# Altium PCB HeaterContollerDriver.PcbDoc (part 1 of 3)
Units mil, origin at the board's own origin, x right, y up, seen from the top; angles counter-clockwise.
Board outline 11550 x 4775 mil, 6 copper layers (Top Layer, GND1, P, N, GND2, Bottom Layer), stack 62.668 mil thick; 274 components, 133 nets, 711 pads, 145 vias.
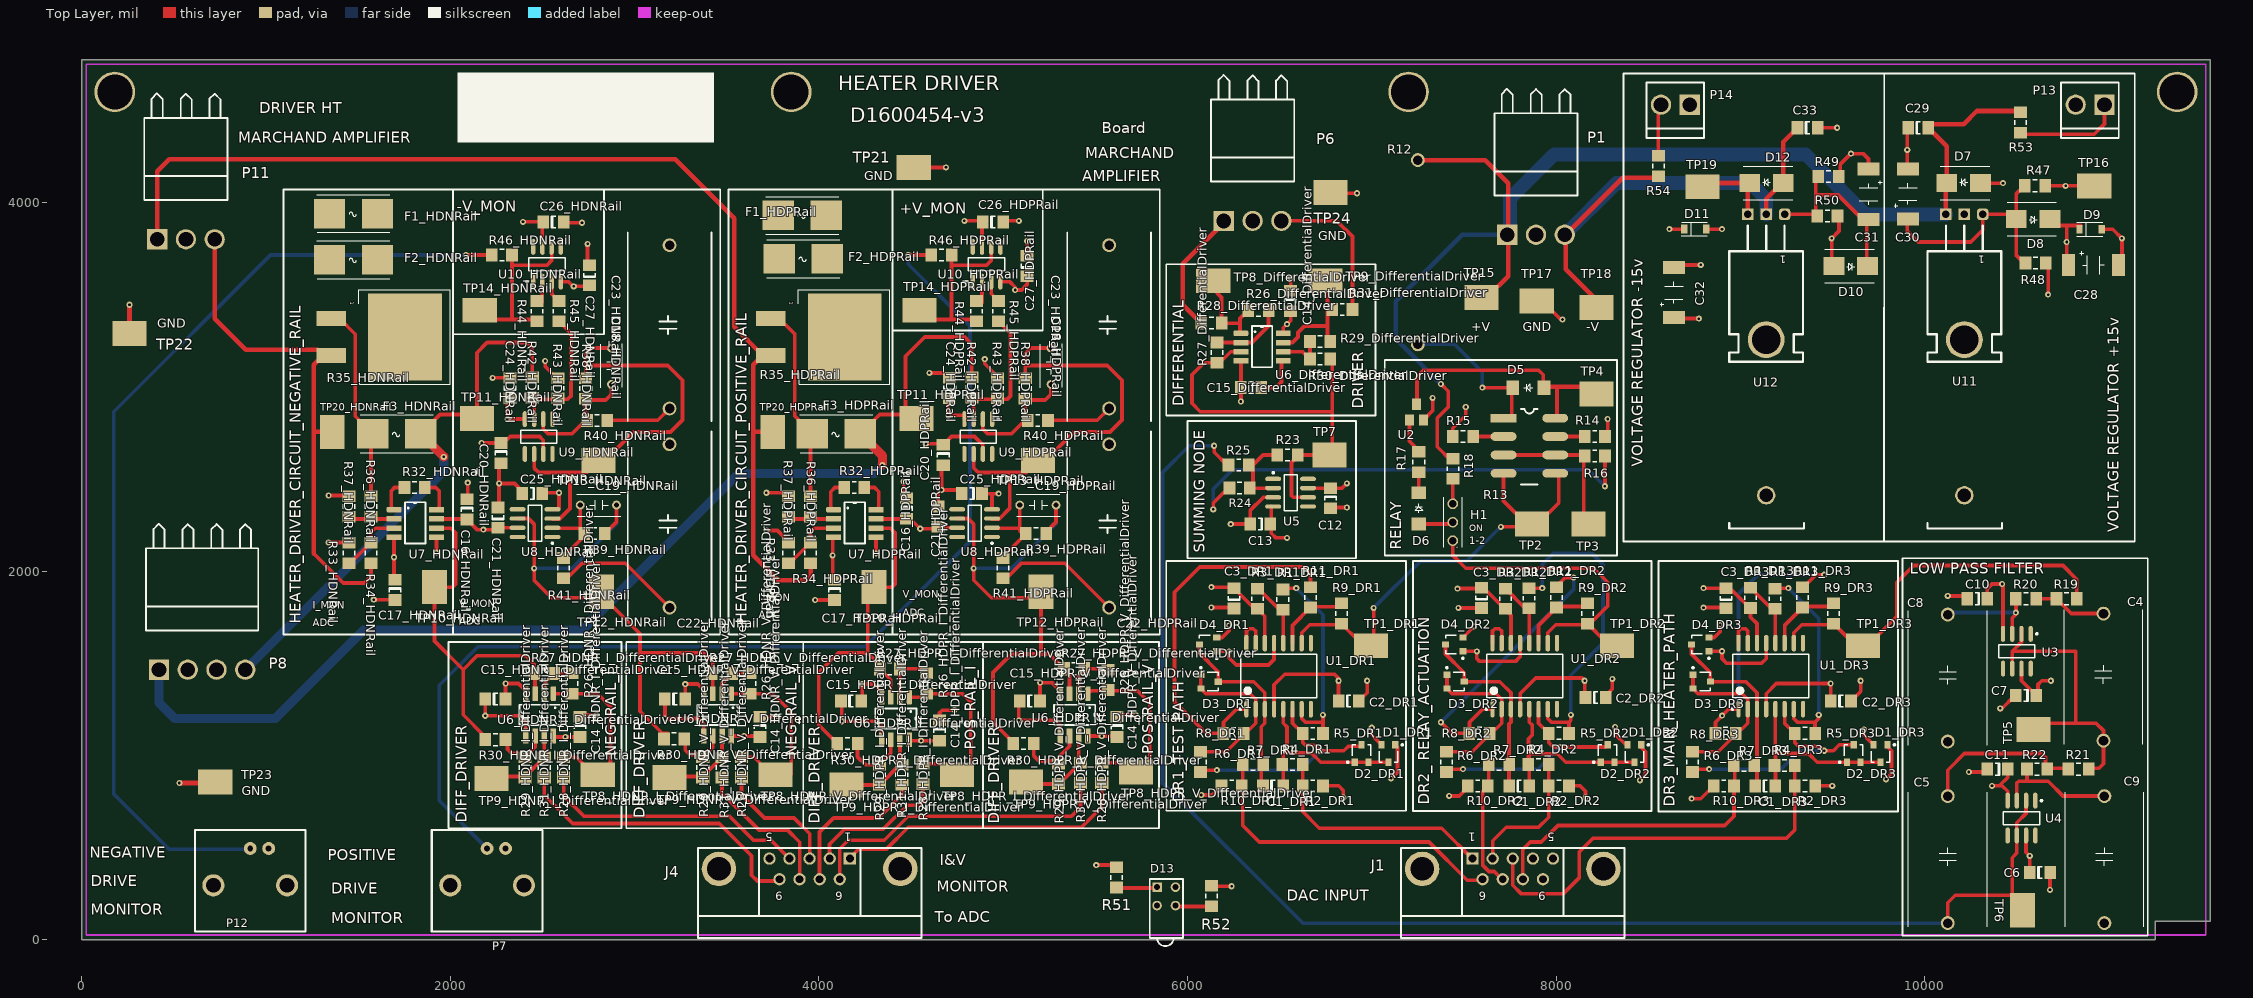
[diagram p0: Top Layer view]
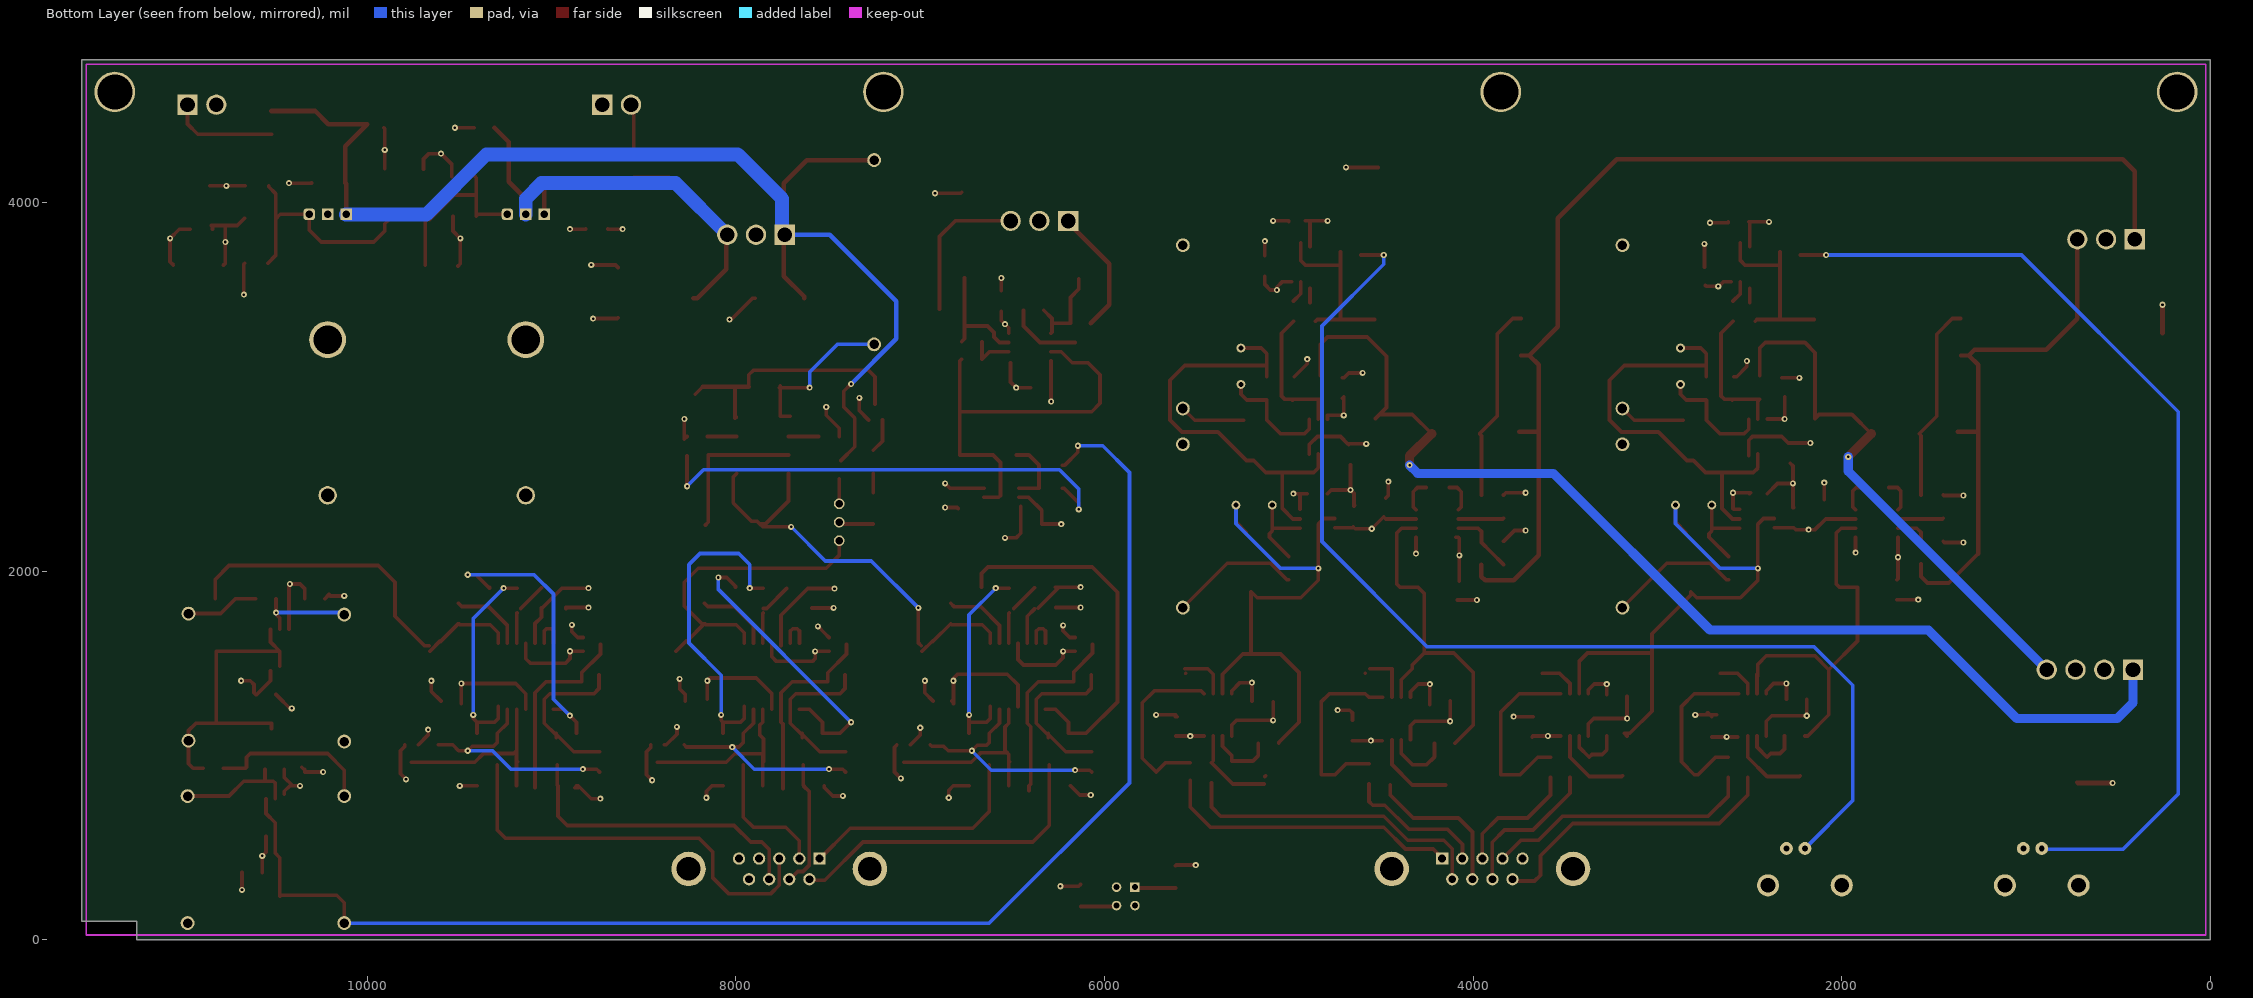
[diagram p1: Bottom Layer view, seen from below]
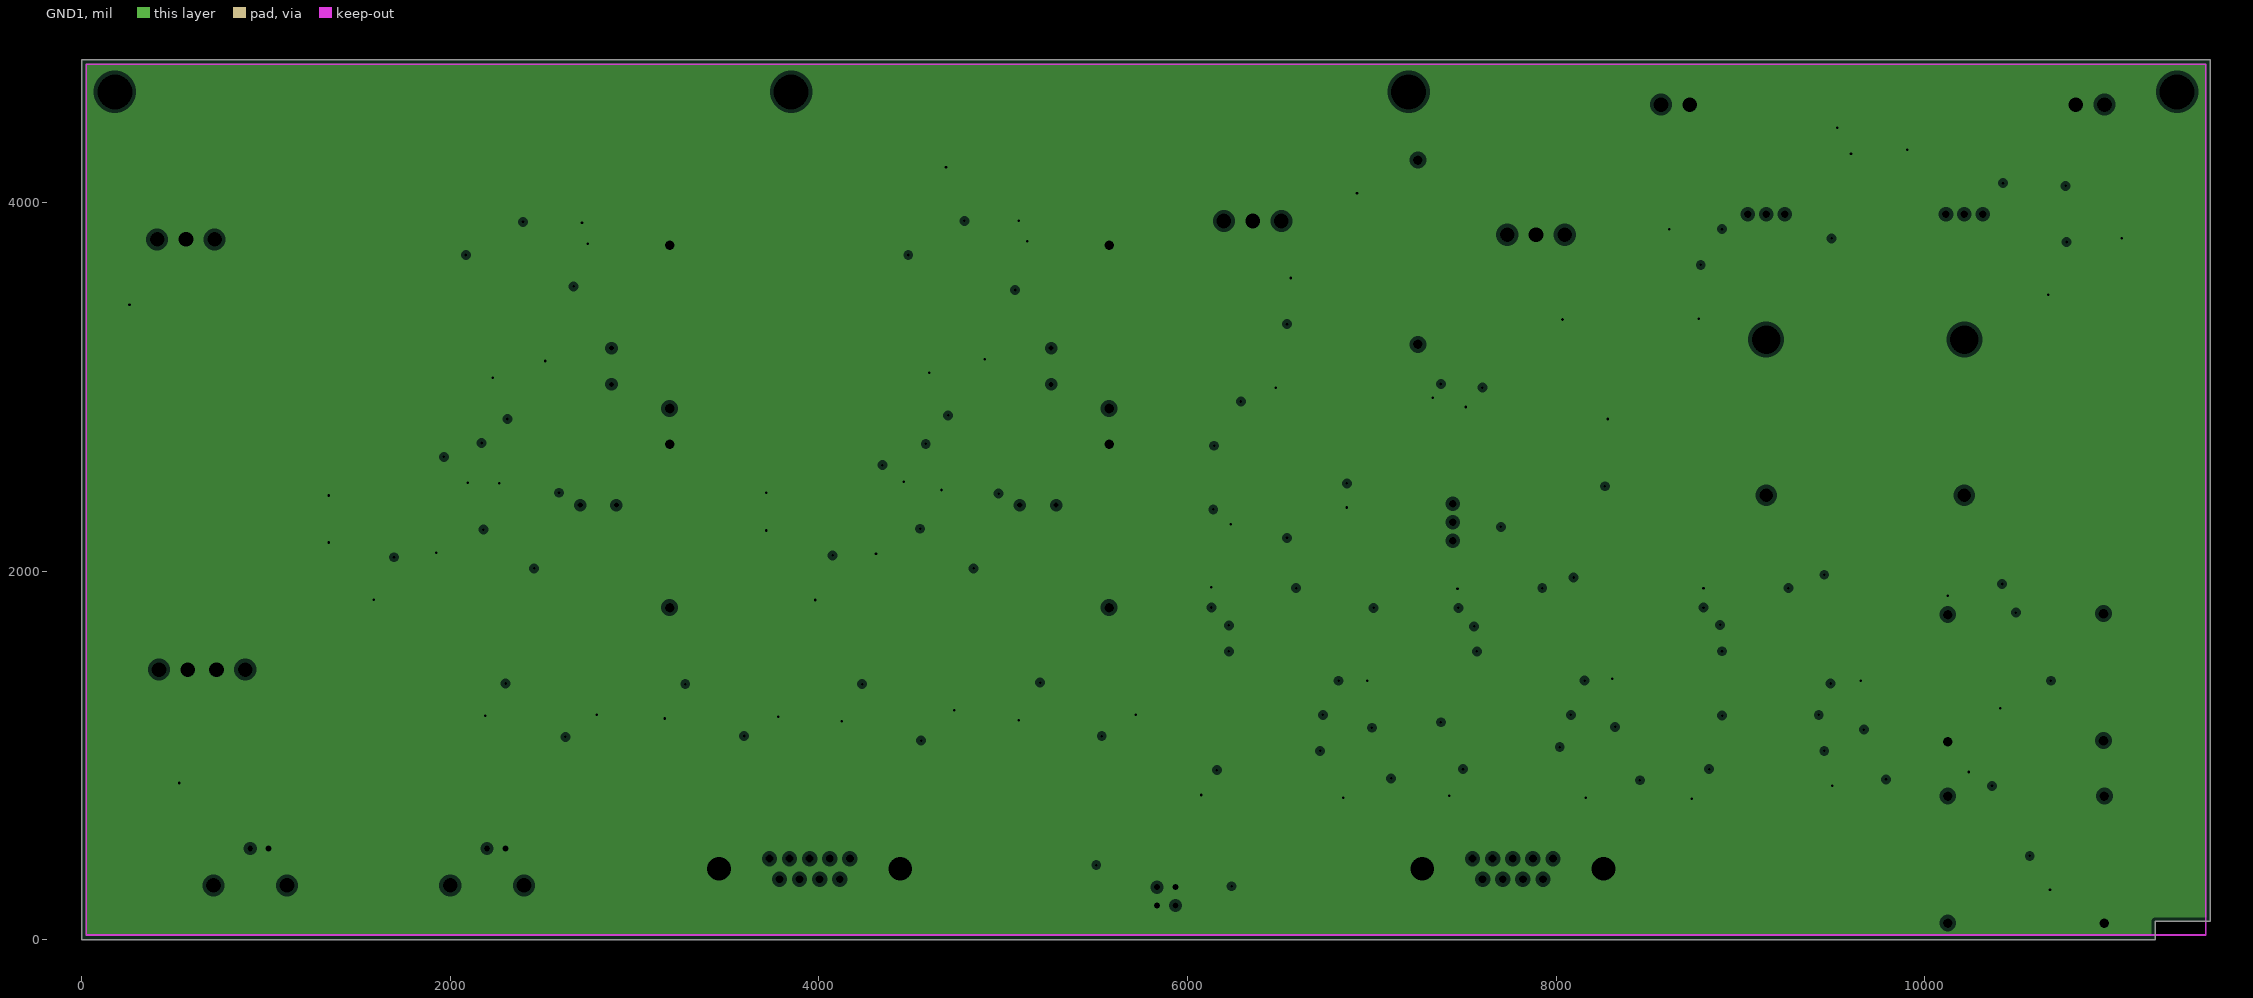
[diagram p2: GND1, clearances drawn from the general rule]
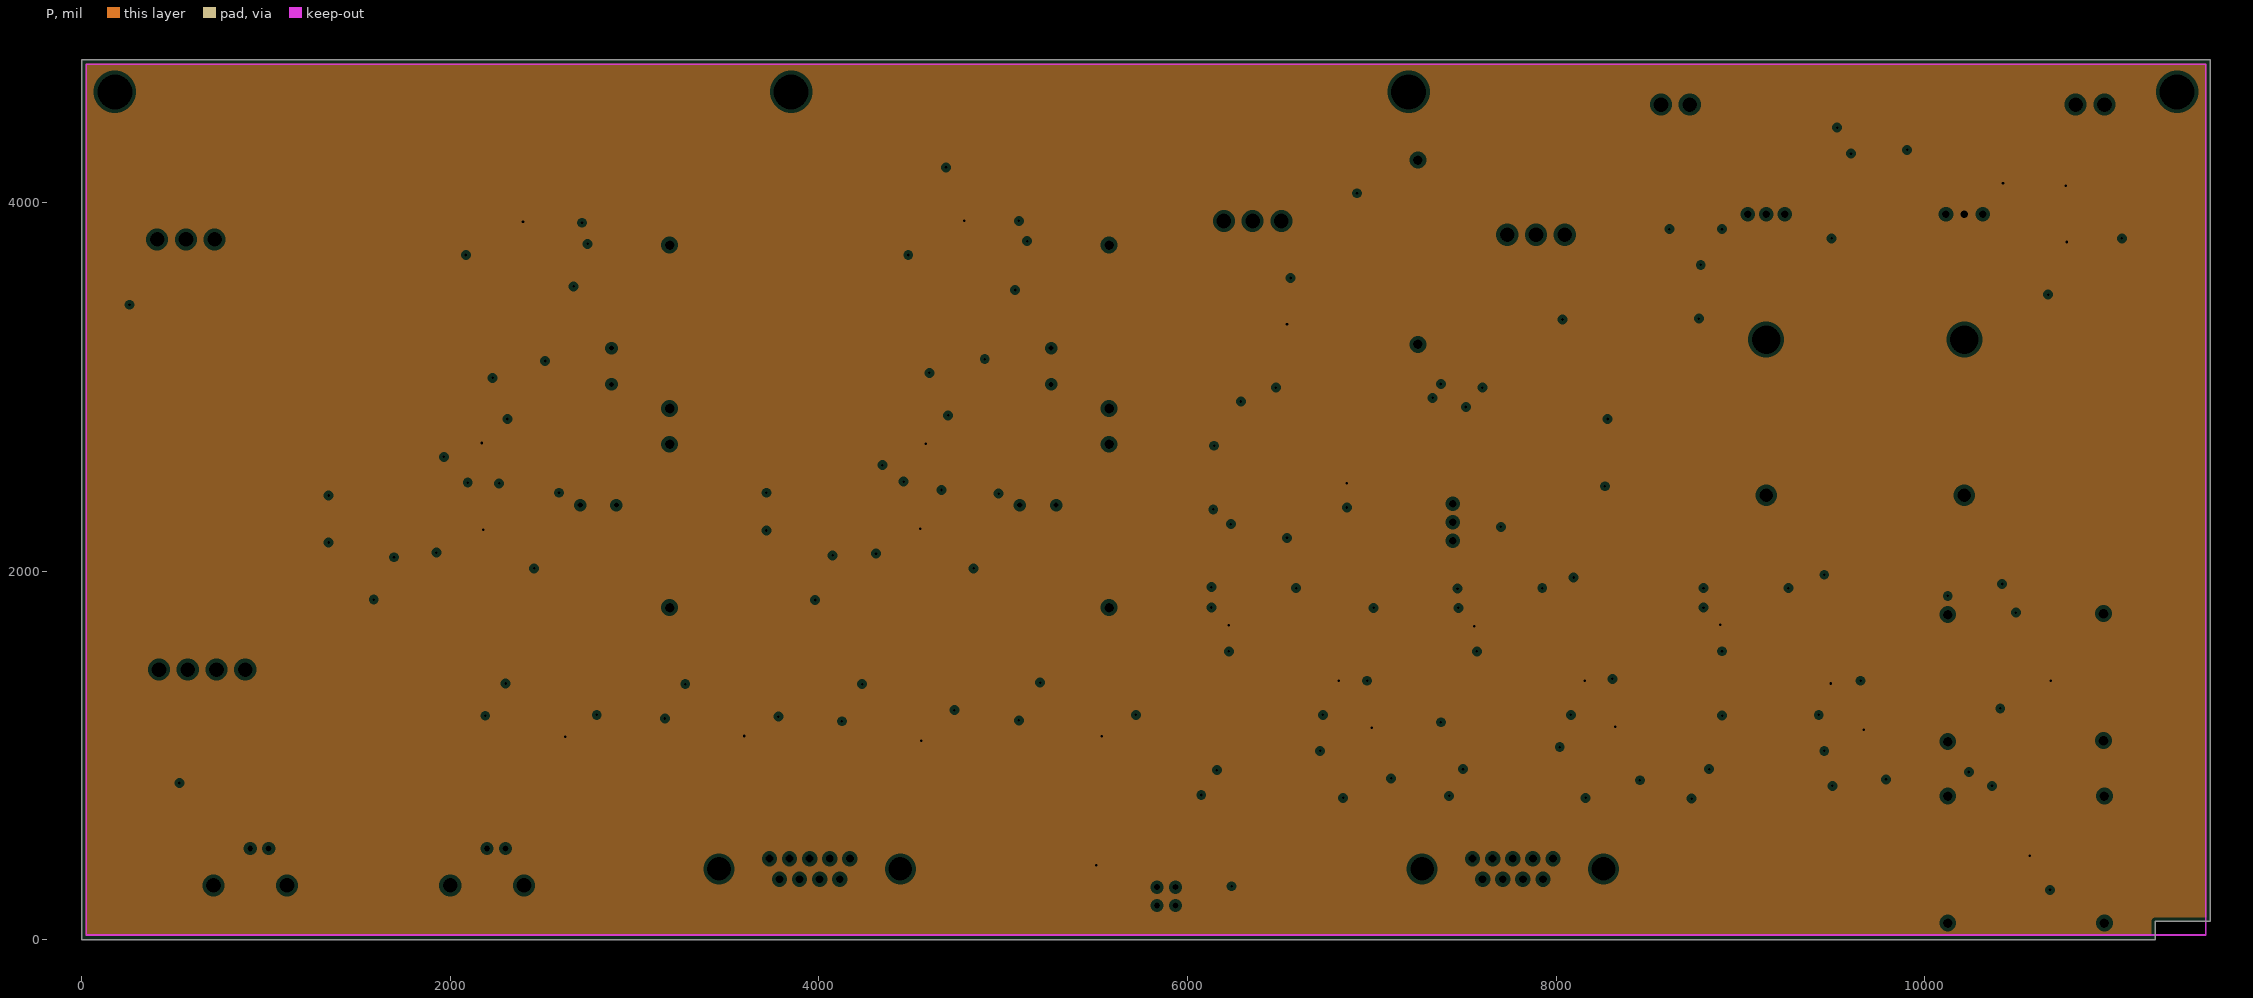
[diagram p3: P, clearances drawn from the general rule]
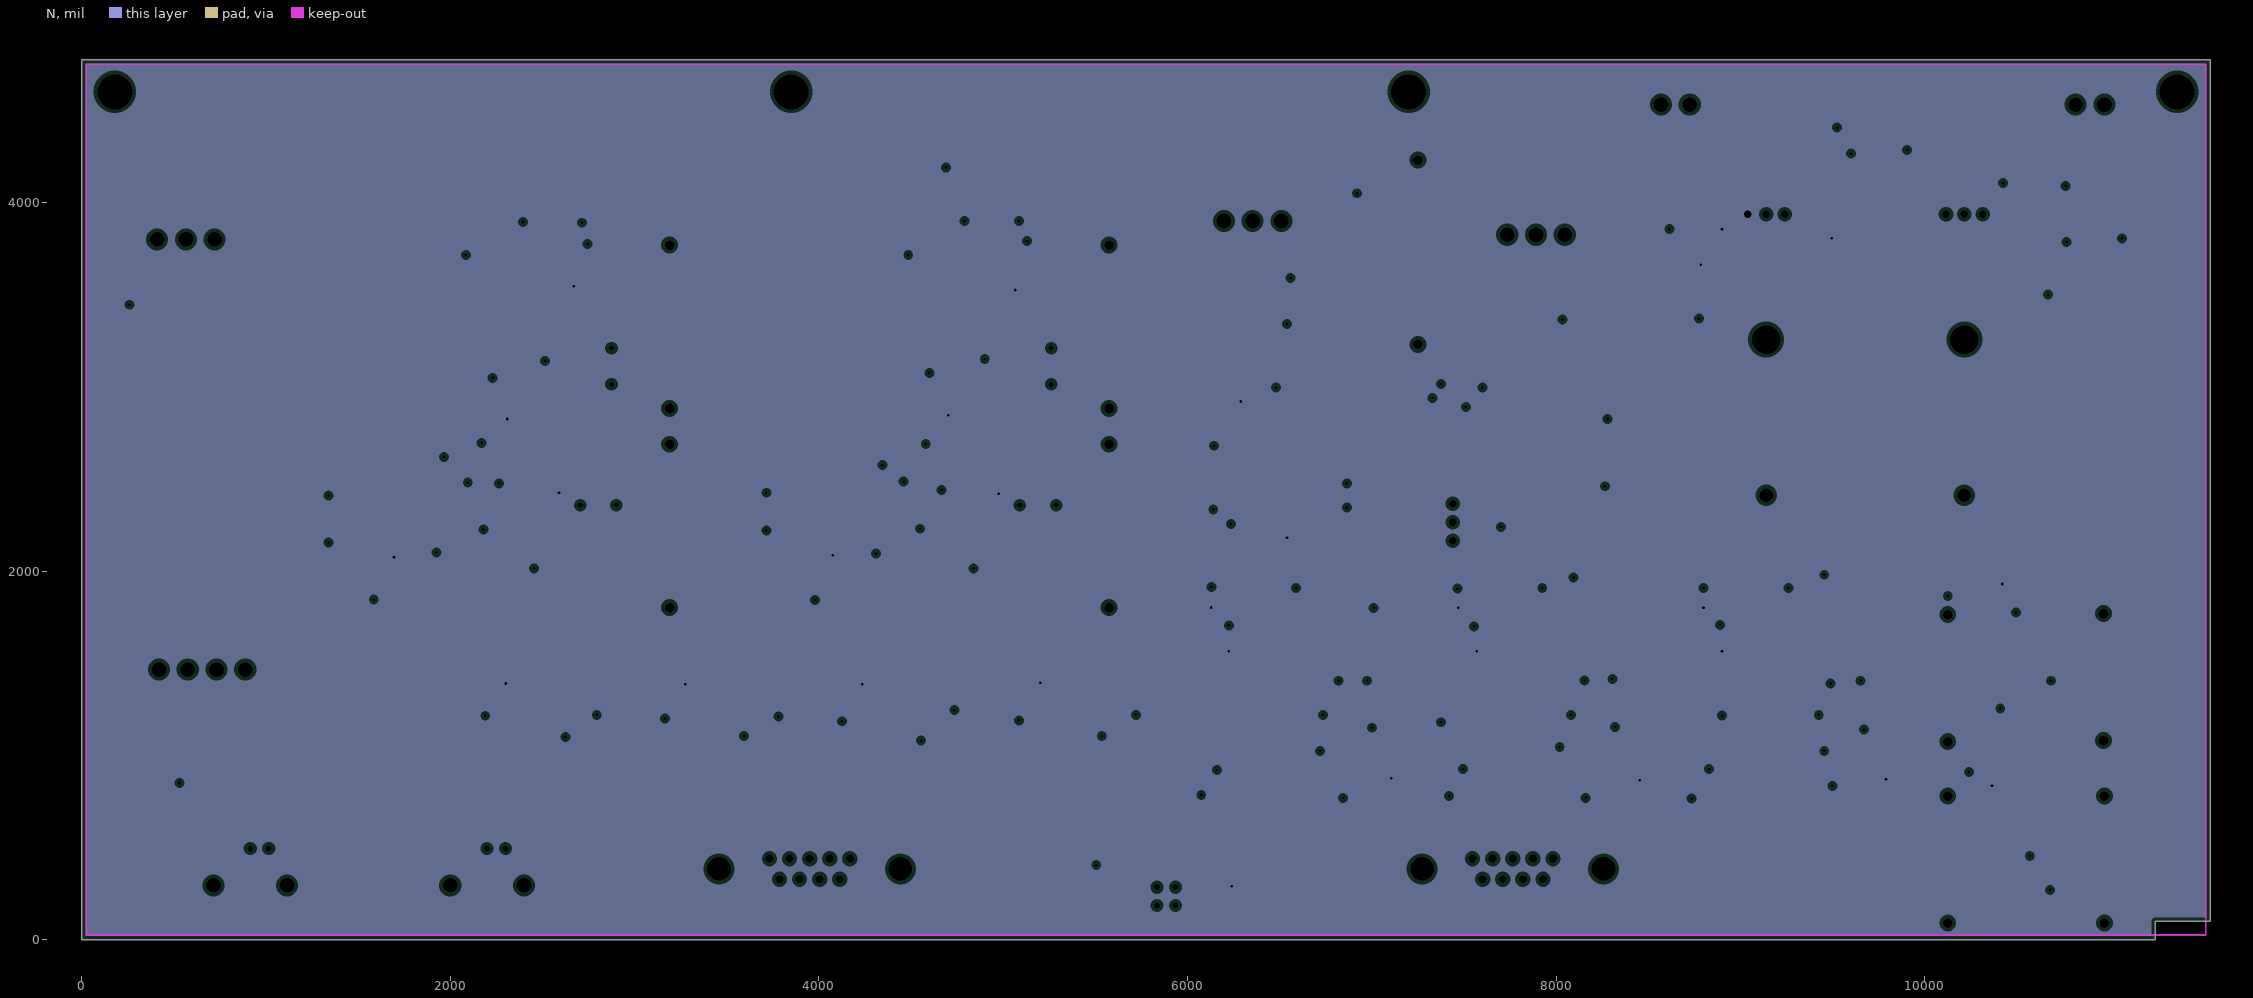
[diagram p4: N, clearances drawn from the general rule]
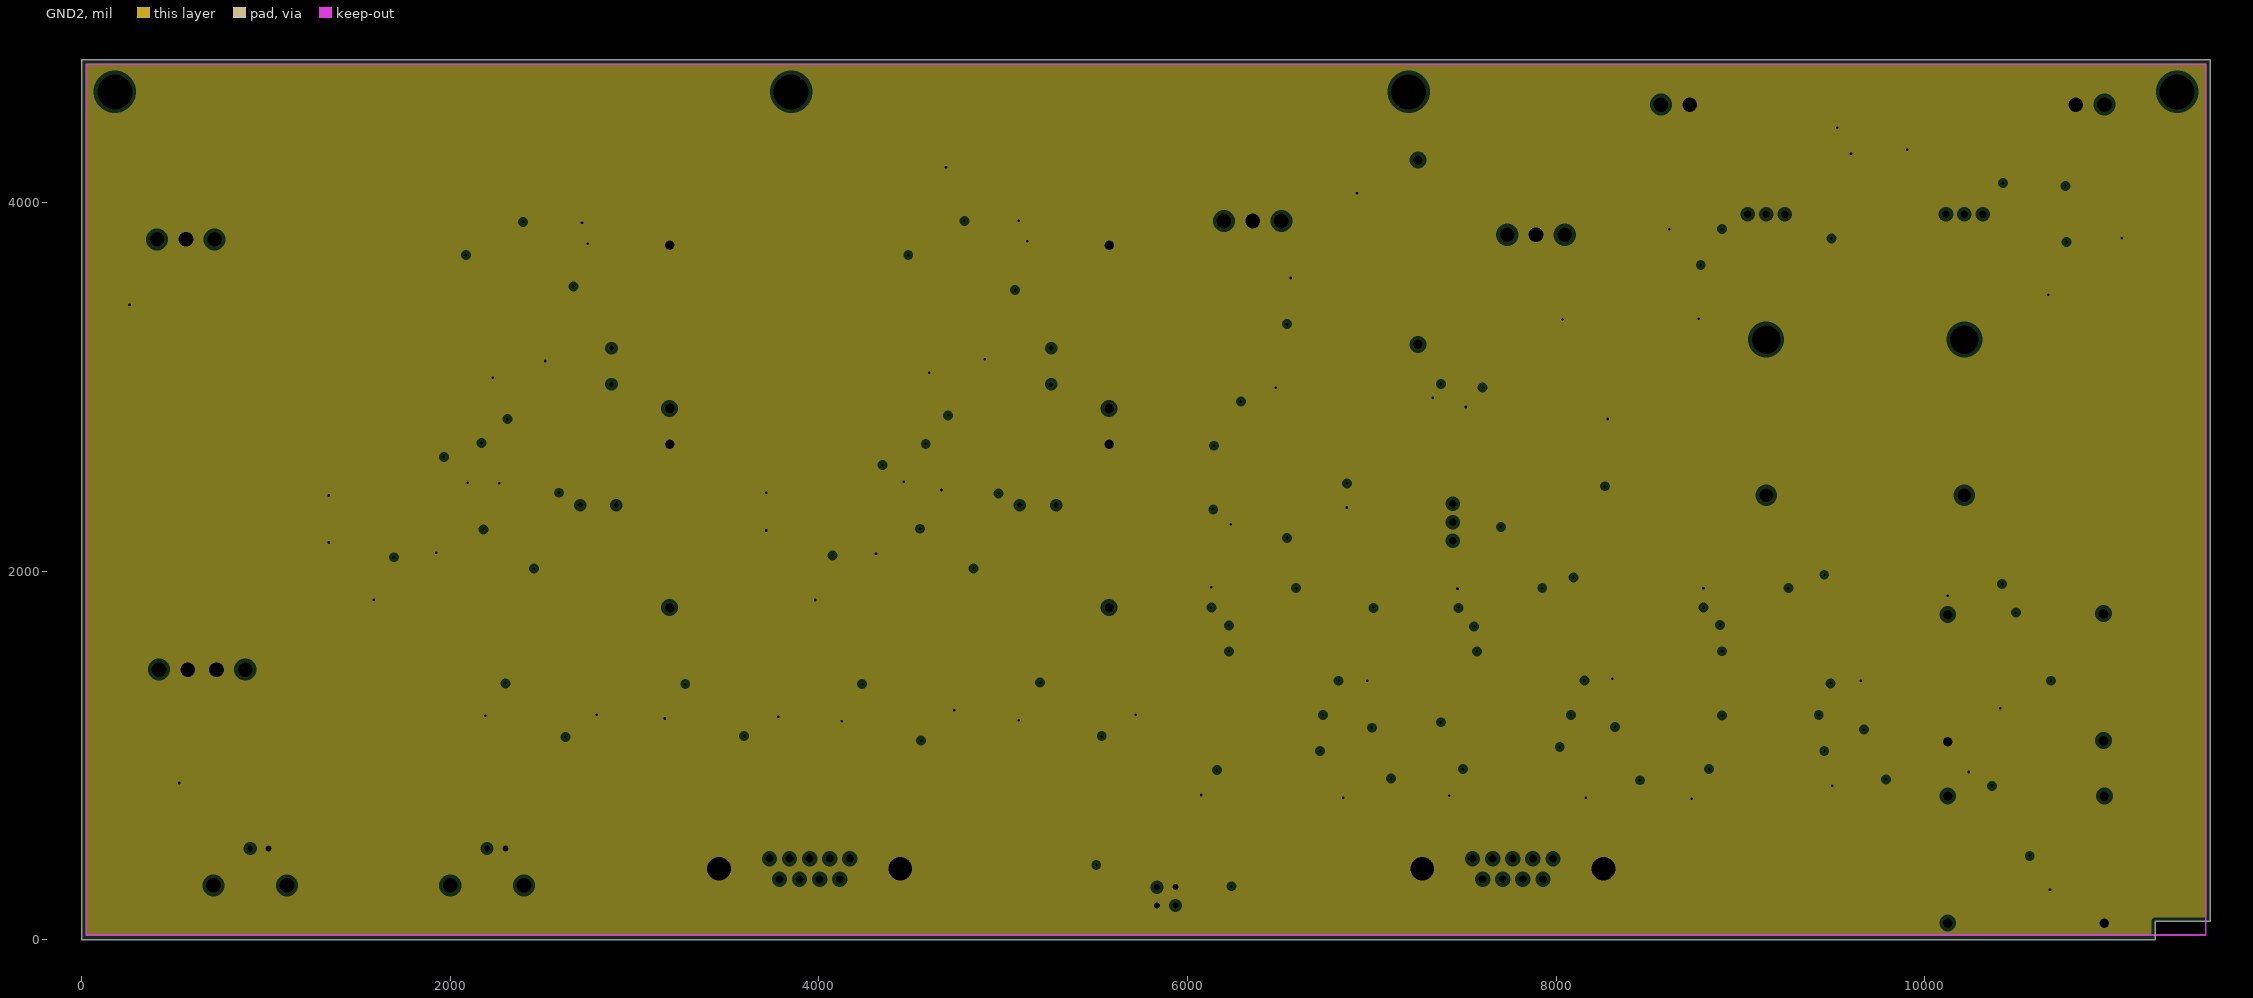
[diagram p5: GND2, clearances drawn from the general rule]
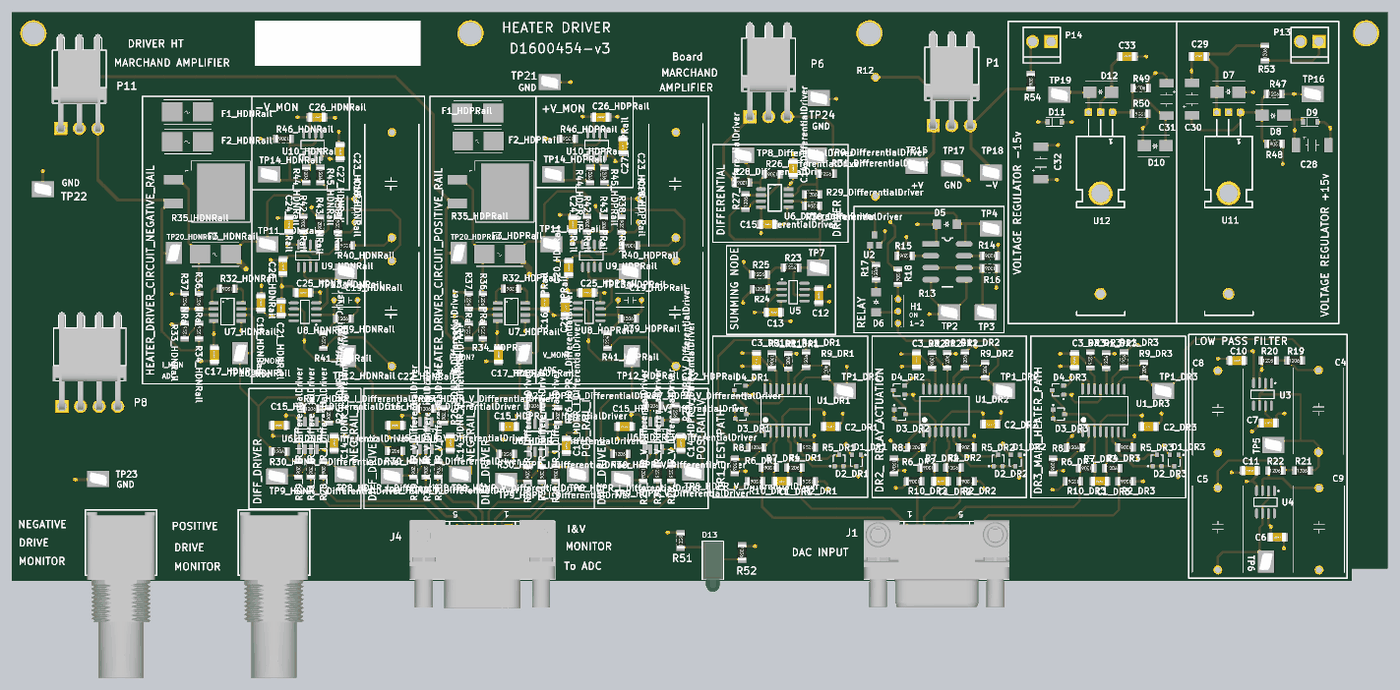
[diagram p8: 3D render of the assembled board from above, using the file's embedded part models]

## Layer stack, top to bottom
Top Solder: solder mask 1, Solder Resist, Dk 3.5
Top Layer: signal copper 2.4
Dielectric 1: prepreg 2.8, PP-006, Dk 4.1
GND1: plane copper 1.417, net GND
Dielectric 2: core 21, Core-037, Dk 4.8
P: plane copper 1.417, net +15
Dielectric 3: prepreg 4.6, PP-016, Dk 4.4
N: plane copper 1.417, net -15
Dielectric 4: core 21, Core-037, Dk 4.8
GND2: plane copper 1.417, net GND
Dielectric 5: prepreg 2.8, PP-006, Dk 4.1
Bottom Layer: signal copper 2.4
Bottom Solder: solder mask 1, Solder Resist, Dk 3.5

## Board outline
0,0 11250,0 11250,100 11550,100 11550,4775 0,4775

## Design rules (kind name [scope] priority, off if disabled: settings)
Clearance [All] p1: gap=10 ignorepadtopadclearanceinfootprint=FALSE except(0: Arc-Hole Track-Hole SMDPad-Hole THPad-Hole Via-Hole Fill-Hole Poly-Hole Region-Hole Text-Hole)
FanoutControl Fanout_Small [(CompPinCount < 5)] p4: bgadir=Out bgaviamode=Centered fanoutstyle=Auto fanoutdirection=InThenOut viagrid=1 // Fanout_Small (Default Rule)
HoleSize [All] p1: absolutevalues=TRUE maxlimit=200 minlimit=1 maxpercent=80.000 minpercent=20.000
MinimumAnnularRing [All] p1: minimumring=9
PlaneClearance [All] p1: clearance=20
PlaneConnect [All] p1: planeconnectstyle=Relief reliefexpansion=20 reliefentries=4 reliefconductorwidth=10 reliefairgap=10
PolygonConnect [All] p1: connectstyle=Relief reliefconductorwidth=10 reliefentries=4 polygonreliefangle="90 Angle" airgapwidth=10
RoomDefinition HeaterDriver [InComponentClass('HeaterDriver')] p1 off: confinementstyle=ConfineIn formatcopy=TRUE lockcomponents=FALSE outline 220,0 9870,0 9870,1675 220,1675
RoomDefinition OPAMP_SUM [InComponentClass('OPAMP_SUM')] p2: confinementstyle=ConfineIn formatcopy=TRUE lockcomponents=FALSE outline 5990,2070 6925,2070 6925,2810 5990,2810
RoomDefinition "Voltage Regulator" [InComponentClass('Voltage Regulator')] p3 off: confinementstyle=ConfineIn formatcopy=TRUE lockcomponents=FALSE outline 7480,2180 11160,2180 11160,4720.5 7480,4720.5
RoomDefinition Relay [InComponentClass('Relay')] p4 off: confinementstyle=ConfineIn formatcopy=TRUE lockcomponents=FALSE outline 7055,2075 8340,2075 8340,4335 7055,4335
RoomDefinition LowPassFilter [InComponentClass('LowPassFilter')] p5: confinementstyle=ConfineIn formatcopy=TRUE lockcomponents=FALSE outline 9870,2085 9870,10 11225,10 11225,2085
RoomDefinition HDPRail [InComponentClass('HDPRail')] p6: confinementstyle=ConfineIn formatcopy=TRUE lockcomponents=FALSE outline 3500,1645 5860,1645 5860,4080 3500,4080
RoomDefinition HDPR_V_DifferentialDriver [InComponentClass('HDPR_V_DifferentialDriver')] p7: confinementstyle=ConfineIn formatcopy=TRUE lockcomponents=FALSE outline 4880,594.88 5840,594.88 5840,1625 4880,1625
RoomDefinition HDPR_I_DifferentialDriver [InComponentClass('HDPR_I_DifferentialDriver')] p8: confinementstyle=ConfineIn formatcopy=TRUE lockcomponents=FALSE outline 3905,595 4865,595 4865,1625.12 3905,1625.12
RoomDefinition HDNRail [InComponentClass('HDNRail')] p9: confinementstyle=ConfineIn formatcopy=TRUE lockcomponents=FALSE outline 1085,1645 3475,1645 3475,4080 1085,4080
RoomDefinition HDNR_V_DifferentialDriver [InComponentClass('HDNR_V_DifferentialDriver')] p10: confinementstyle=ConfineIn formatcopy=TRUE lockcomponents=FALSE outline 2945,594.88 3905,594.88 3905,1625 2945,1625
RoomDefinition HDNR_I_DifferentialDriver [InComponentClass('HDNR_I_DifferentialDriver')] p11: confinementstyle=ConfineIn formatcopy=TRUE lockcomponents=FALSE outline 1980.12,595 2940.12,595 2940.12,1625.12 1980.12,1625.12
RoomDefinition DR3 [InComponentClass('DR3')] p12: confinementstyle=ConfineIn formatcopy=TRUE lockcomponents=FALSE outline 8545,684.88 9865,684.88 9865,2070 8545,2070
RoomDefinition DR2 [InComponentClass('DR2')] p13: confinementstyle=ConfineIn formatcopy=TRUE lockcomponents=FALSE outline 7210,684.88 8530,684.88 8530,2070 7210,2070
RoomDefinition DR1 [InComponentClass('DR1')] p14: confinementstyle=ConfineIn formatcopy=TRUE lockcomponents=FALSE outline 5875,684.76 7195,684.76 7195,2069.88 5875,2069.88
RoomDefinition DifferentialDriver [InComponentClass('DifferentialDriver')] p15: confinementstyle=ConfineIn formatcopy=FALSE lockcomponents=FALSE outline 5875,2850 7029.76,2850 7029.76,3675 5875,3675
RoutingVias [All] p1: holewidth=14 width=33 viastyle="Through Hole" minholewidth=10 minwidth=10 maxholewidth=28 maxwidth=50
SilkToSolderMaskClearance [IsPad] p1: minsilkscreentomaskgap=7 clearancetoexposedcopper=TRUE
SolderMaskExpansion [All] p1: expansion=4 istentingtop=FALSE
SupplyNets "Schematic Supply Nets_4" [InNet('+15')] p1: voltage=0.000
SupplyNets "Schematic Supply Nets_3" [InNet('GND')] p2: voltage=0.000
SupplyNets "Schematic Supply Nets_2" [InNet('+18')] p3: voltage=0.000
SupplyNets "Schematic Supply Nets_1" [InNet('-18')] p4: voltage=0.000
SupplyNets "Schematic Supply Nets" [InNet('-15')] p5: voltage=0.000
Width [All] p1: maxlimit=100 minlimit=10 preferedwidth=20
25 further rules are at their usual default settings.

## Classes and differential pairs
channel class HeaterDriverCircuit: HDNRail HDPRail
channel class DifferentialDriver: DifferentialDriver HDNR_I_DifferentialDriver HDNR_V_DifferentialDriver HDPR_I_DifferentialDriver HDPR_V_DifferentialDriver
component class "Voltage Regulator": C28 C29 C30 C31 C32 C33 D7 D8 D9 D10 D11 D12 P13 P14 P16 Part8 Part9 R47 R48 R49 R50 R53 R54 TP15 TP16 TP17 TP18 TP19 TP21 TP22 TP23 TP24 U11 U12
component class Relay: D5 D6 H1 Part7 R12 R13 R14 R15 R16 R17 R18 TP2 TP3 TP4 U2
component class OPAMP_SUM: C12 C13 R23 R24 R25 TP7 U5
component class LowPassFilter: C4 C5 C6 C7 C8 C9 C10 C11 R19 R20 R21 R22 TP5 TP6 U3 U4
component class HDPRail: C16_HDPRail C17_HDPRail C18_HDPRail C19_HDPRail C20_HDPRail C21_HDPRail C22_HDPRail C23_HDPRail C24_HDPRail C25_HDPRail C26_HDPRail C27_HDPRail F1_HDPRail F2_HDPRail F3_HDPRail R32_HDPRail R33_HDPRail R34_HDPRail R35_HDPRail R36_HDPRail R37_HDPRail R38_HDPRail R39_HDPRail R40_HDPRail R41_HDPRail R42_HDPRail R43_HDPRail R44_HDPRail R45_HDPRail R46_HDPRail TP10_HDPRail TP11_HDPRail TP12_HDPRail TP13_HDPRail TP14_HDPRail TP20_HDPRail U7_HDPRail U8_HDPRail U9_HDPRail U10_HDPRail
component class HDPR_V_DifferentialDriver: C14_HDPR_V_DifferentialDriver C15_HDPR_V_DifferentialDriver R26_HDPR_V_DifferentialDriver R27_HDPR_V_DifferentialDriver R28_HDPR_V_DifferentialDriver R29_HDPR_V_DifferentialDriver R30_HDPR_V_DifferentialDriver R31_HDPR_V_DifferentialDriver TP8_HDPR_V_DifferentialDriver TP9_HDPR_V_DifferentialDriver U6_HDPR_V_DifferentialDriver
component class HDPR_I_DifferentialDriver: C14_HDPR_I_DifferentialDriver C15_HDPR_I_DifferentialDriver R26_HDPR_I_DifferentialDriver R27_HDPR_I_DifferentialDriver R28_HDPR_I_DifferentialDriver R29_HDPR_I_DifferentialDriver R30_HDPR_I_DifferentialDriver R31_HDPR_I_DifferentialDriver TP8_HDPR_I_DifferentialDriver TP9_HDPR_I_DifferentialDriver U6_HDPR_I_DifferentialDriver
component class HDNRail: C16_HDNRail C17_HDNRail C18_HDNRail C19_HDNRail C20_HDNRail C21_HDNRail C22_HDNRail C23_HDNRail C24_HDNRail C25_HDNRail C26_HDNRail C27_HDNRail F1_HDNRail F2_HDNRail F3_HDNRail R32_HDNRail R33_HDNRail R34_HDNRail R35_HDNRail R36_HDNRail R37_HDNRail R38_HDNRail R39_HDNRail R40_HDNRail R41_HDNRail R42_HDNRail R43_HDNRail R44_HDNRail R45_HDNRail R46_HDNRail TP10_HDNRail TP11_HDNRail TP12_HDNRail TP13_HDNRail TP14_HDNRail TP20_HDNRail U7_HDNRail U8_HDNRail U9_HDNRail U10_HDNRail
component class HDNR_V_DifferentialDriver: C14_HDNR_V_DifferentialDriver C15_HDNR_V_DifferentialDriver R26_HDNR_V_DifferentialDriver R27_HDNR_V_DifferentialDriver R28_HDNR_V_DifferentialDriver R29_HDNR_V_DifferentialDriver R30_HDNR_V_DifferentialDriver R31_HDNR_V_DifferentialDriver TP8_HDNR_V_DifferentialDriver TP9_HDNR_V_DifferentialDriver U6_HDNR_V_DifferentialDriver
component class HDNR_I_DifferentialDriver: C14_HDNR_I_DifferentialDriver C15_HDNR_I_DifferentialDriver R26_HDNR_I_DifferentialDriver R27_HDNR_I_DifferentialDriver R28_HDNR_I_DifferentialDriver R29_HDNR_I_DifferentialDriver R30_HDNR_I_DifferentialDriver R31_HDNR_I_DifferentialDriver TP8_HDNR_I_DifferentialDriver TP9_HDNR_I_DifferentialDriver U6_HDNR_I_DifferentialDriver
component class DifferentialDriver: C14_DifferentialDriver C15_DifferentialDriver R26_DifferentialDriver R27_DifferentialDriver R28_DifferentialDriver R29_DifferentialDriver R30_DifferentialDriver R31_DifferentialDriver TP8_DifferentialDriver TP9_DifferentialDriver U6_DifferentialDriver
component class DR1: C1_DR1 C2_DR1 C3_DR1 D1_DR1 D2_DR1 D3_DR1 D4_DR1 R1_DR1 R2_DR1 R3_DR1 R4_DR1 R5_DR1 R6_DR1 R7_DR1 R8_DR1 R9_DR1 R10_DR1 R11_DR1 TP1_DR1 U1_DR1
component class DR2: C1_DR2 C2_DR2 C3_DR2 D1_DR2 D2_DR2 D3_DR2 D4_DR2 R1_DR2 R2_DR2 R3_DR2 R4_DR2 R5_DR2 R6_DR2 R7_DR2 R8_DR2 R9_DR2 R10_DR2 R11_DR2 TP1_DR2 U1_DR2
component class DR3: C1_DR3 C2_DR3 C3_DR3 D1_DR3 D2_DR3 D3_DR3 D4_DR3 R1_DR3 R2_DR3 R3_DR3 R4_DR3 R5_DR3 R6_DR3 R7_DR3 R8_DR3 R9_DR3 R10_DR3 R11_DR3 TP1_DR3 U1_DR3
component class HeaterDriver: D13 J1 "J1     DAC INPUT" "J2     DAC Output" "J3  POWER HEATER" J4 P1 P6 P7 P8 P11 P12 R51 R52
channel class DiffRec: DR1 DR2 DR3

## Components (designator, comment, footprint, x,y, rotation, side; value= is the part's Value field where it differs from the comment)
C1_DR1 "3.3nF" CC3216-1206 6465,834.76 r0 top (schematic designator C1)
C1_DR2 "3.3nF" CC3216-1206 7800,834.88 r0 top (schematic designator C1)
C1_DR3 "3.3nF" CC3216-1206 9135,834.88 r0 top (schematic designator C1)
C2_DR1 "1UF" CC3216-1206 6875,1294.76 r0 top value=1uF (schematic designator C2)
C2_DR2 "1UF" CC3216-1206 8215,1315 r0 top value=1uF (schematic designator C2)
C2_DR3 "1UF" CC3216-1206 9545,1294.88 r0 top value=1uF (schematic designator C2)
C3_DR1 "1UF" CC3216-1206 6252.24,1852.28 r90 top value=1uF (schematic designator C3)
C3_DR2 "1UF" CC3216-1206 7595,1855 r90 top value=1uF (schematic designator C3)
C3_DR3 "1UF" CC3216-1206 8922.24,1852.4 r90 top value=1uF (schematic designator C3)
C4 "Cap Film 3.9uF 250v 10%" CAP_FILM_0.689INCH 10970,1080 r90 top value=3.9uF
C5 "Cap Film 3.9uF 250v 10%" CAP_FILM_0.689INCH 10125,90 r90 top value=3.9uF
C6 "1UF" CC3216-1206 10625,365 r0 top value=1uF
C7 "1UF" CC3216-1206 10550,1325 r180 top value=1uF
C8 "Cap Film 3.9uF 250v 10%" CAP_FILM_0.689INCH 10125,1075 r90 top value=3.9uF
C9 "Cap Film 3.9uF 250v 10%" CAP_FILM_0.689INCH 10975,90 r90 top value=3.9uF
C10 "1UF" CC3216-1206 10285,1850 r180 top value=1uF
C11 "1UF" CC3216-1206 10395,925 r180 top value=1uF
C12 "1UF" CC3216-1206 6775,2395 r270 top value=1uF
C13 "1UF" CC3216-1206 6395,2255 r180 top value=1uF
C14_DifferentialDriver "1UF" CC3216-1206 6560,3465 r270 top value=1uF (schematic designator C14)
C14_HDNR_I_DifferentialDriver "1UF" CC3216-1206 2705,1155 r270 top value=1uF (schematic designator C14)
C14_HDNR_V_DifferentialDriver "1UF" CC3216-1206 3680,1155 r270 top value=1uF (schematic designator C14)
C14_HDPR_I_DifferentialDriver "1UF" CC3216-1206 4655,1135 r270 top value=1uF (schematic designator C14)
C14_HDPR_V_DifferentialDriver "1UF" CC3216-1206 5616.88,1154.88 r270 top value=1uF (schematic designator C14)
C15_DifferentialDriver "1UF" CC3216-1206 6344.61,2995 r180 top value=1uF (schematic designator C15)
C15_HDNR_I_DifferentialDriver "1UF" CC3216-1206 2245,1305 r0 top value=1uF (schematic designator C15)
C15_HDNR_V_DifferentialDriver "1UF" CC3216-1206 3220,1305 r0 top value=1uF (schematic designator C15)
C15_HDPR_I_DifferentialDriver "1UF" CC3216-1206 4175,1294.88 r0 top value=1uF (schematic designator C15)
C15_HDPR_V_DifferentialDriver "1UF" CC3216-1206 5145,1294.65 r0 top value=1uF (schematic designator C15)
C16_HDNRail "1UF" CC3216-1206 2090,2335 r270 top value=1uF (schematic designator C16)
C16_HDPRail "1UF" CC3216-1206 4475,2339.88 r270 top value=1uF (schematic designator C16)
C17_HDNRail "1UF" CC3216-1206 1700,1898 r270 top value=1uF (schematic designator C17)
C17_HDPRail "1UF" CC3216-1206 4085,1898 r270 top value=1uF (schematic designator C17)
C18_HDNRail "Cap Film 6.8nF 100V 5% Polyester 0.197inch" CAP_FILM_POLY_0.197INCH 2875,3013 r90 top value=6.8nF (schematic designator C18)
C18_HDPRail "Cap Film 6.8nF 100V 5% Polyester 0.197inch" CAP_FILM_POLY_0.197INCH 5260,3013 r90 top value=6.8nF (schematic designator C18)
C19_HDNRail "Cap Film 6.8nF 100V 5% Polyester 0.197inch" CAP_FILM_POLY_0.197INCH 2705,2358 r0 top value=6.8nF (schematic designator C19)
C19_HDPRail "Cap Film 6.8nF 100V 5% Polyester 0.197inch" CAP_FILM_POLY_0.197INCH 5090,2358 r0 top value=6.8nF (schematic designator C19)
C20_HDNRail "1UF" CC3216-1206 2275,2640 r270 top value=1uF (schematic designator C20)
C20_HDPRail "1UF" CC3216-1206 4675,2630 r270 top value=1uF (schematic designator C20)
C21_HDNRail "1UF" CC3216-1206 2260,2290 r90 top value=1uF (schematic designator C21)
C21_HDPRail "1UF" CC3216-1206 4646.88,2295 r90 top value=1uF (schematic designator C21)
C22_HDNRail "Cap Film 10uF 100v 0.886inch" CAP_FILM_0.886INCH 3190,2688 r270 top value=10uF (schematic designator C22)
C22_HDPRail "Cap Film 10uF 100v 0.886inch" CAP_FILM_0.886INCH 5575,2688 r270 top value=10uF (schematic designator C22)
C23_HDNRail "Cap Film 10uF 100v 0.886inch" CAP_FILM_0.886INCH 3190,3768 r270 top value=10uF (schematic designator C23)
C23_HDPRail "Cap Film 10uF 100v 0.886inch" CAP_FILM_0.886INCH 5575,3768 r270 top value=10uF (schematic designator C23)
C24_HDNRail "1UF" CC3216-1206 2325,2993 r90 top value=1uF (schematic designator C24)
C24_HDPRail "1UF" CC3216-1206 4710,2993 r90 top value=1uF (schematic designator C24)
C25_HDNRail "1UF" CC3216-1206 2445,2419.88 r180 top value=1uF (schematic designator C25)
C25_HDPRail "1UF" CC3216-1206 4830,2420 r180 top value=1uF (schematic designator C25)
C26_HDNRail "1UF" CC3216-1206 2560,3895 r0 top value=1uF (schematic designator C26)
C26_HDPRail "1UF" CC3216-1206 4945,3895 r0 top value=1uF (schematic designator C26)
C27_HDNRail "1UF" CC3216-1206 2755,3605 r90 top value=1uF (schematic designator C27)
C27_HDPRail "1UF" CC3216-1206 5130,3655 r90 top value=1uF (schematic designator C27)
C28 "SMD Cap Tantalum Poly 10uF 50v 2917" 2916 10780,3660 r0 top value="10µF 50v"
C29 "1UF" CC3216-1206 9965,4405.5 r0 top value=1uF
C30 "SMD Cap Tantalum Poly 10uF 50v 2917" 2916 9909,3910.5 r90 top value="10µF 50v"
C31 "SMD Cap Tantalum Poly 10uF 50v 2917" 2916 9695.12,4180.5 r270 top value="10µF 50v"
C32 "SMD Cap Tantalum Poly 10uF 50v 2917" 2916 8639.5,3375 r90 top value="10µF 50v"
C33 "1UF" CC3216-1206 9365,4405.5 r0 top value=1uF
D1_DR1 "DualDiode" SOT-23A 7090,1009.76 r180 top value=BAS70-04LT1GOSCT-ND (schematic designator D1)
D1_DR2 "DualDiode" SOT-23A 8425,1009.88 r180 top value=BAS70-04LT1GOSCT-ND (schematic designator D1)
D1_DR3 "DualDiode" SOT-23A 9760,1009.88 r180 top value=BAS70-04LT1GOSCT-ND (schematic designator D1)
D2_DR1 "DualDiode" SOT-23A 6945,1009.76 r0 top value=BAS70-04LT1GOSCT-ND (schematic designator D2)
D2_DR2 "DualDiode" SOT-23A 8280,1009.88 r0 top value=BAS70-04LT1GOSCT-ND (schematic designator D2)
D2_DR3 "DualDiode" SOT-23A 9615,1009.88 r0 top value=BAS70-04LT1GOSCT-ND (schematic designator D2)
D3_DR1 "DualDiode" SOT-23A 6120,1399.88 r270 top value=BAS70-04LT1GOSCT-ND (schematic designator D3)
D3_DR2 "DualDiode" SOT-23A 7455,1400 r270 top value=BAS70-04LT1GOSCT-ND (schematic designator D3)
D3_DR3 "DualDiode" SOT-23A 8790,1400 r270 top value=BAS70-04LT1GOSCT-ND (schematic designator D3)
D4_DR1 "DualDiode" SOT-23A 6112.24,1602.28 r90 top value=BAS70-04LT1GOSCT-ND (schematic designator D4)
D4_DR2 "DualDiode" SOT-23A 7447.24,1602.4 r90 top value=BAS70-04LT1GOSCT-ND (schematic designator D4)
D4_DR3 "DualDiode" SOT-23A 8782.24,1602.4 r90 top value=BAS70-04LT1GOSCT-ND (schematic designator D4)
D5 "Diode General" DIODE_SE20AFJ-M3/6A 7765,2995 r0 top value=SE20AFJ-M3/6AGICT-ND
D6 "Diode General" DIODE_SE20AFJ-M3/6A 7255,2425 r270 top value=SE20AFJ-M3/6AGICT-ND
D7 "Diode Standard 100V 1A Surface Mount SMB" DIODE_SMB 10120,4105.5 r0 top value=S1BB-FDICT-ND
D8 "Diode Standard 100V 1A Surface Mount SMB" DIODE_SMB 10680,3910.5 r180 top value=S1BB-FDICT-ND
D9 "Diode Schottky 60v 1A SMT PMDU SOD-123F" SOD-123F 10840,3855 r0 top value=RB160M-60CT-ND
D10 "Diode Standard 100V 1A Surface Mount SMB" DIODE_SMB 9690,3655.5 r180 top value=S1BB-FDICT-ND
D11 "Diode Schottky 60v 1A SMT PMDU SOD-123F" SOD-123F 8695,3855.5 r0 top value=RB160M-60CT-ND
D12 "Diode Standard 100V 1A Surface Mount SMB" DIODE_SMB 9050,4105.5 r0 top value=S1BB-FDICT-ND
D13 "Stacked LED" "my LUMEX Dual LED" 5835,285 r90 top locked
F1_HDNRail "FUSE BRD MNT 1A 125VAC/VDC 2SMD" "SMD FUSE" 1605,3940 r180 top value="1 AMP" (schematic designator F1)
F1_HDPRail "FUSE BRD MNT 1A 125VAC/VDC 2SMD" "SMD FUSE" 4040,3930 r180 top value="1 AMP" (schematic designator F1)
F2_HDNRail "FUSE BRD MNT 1A 125VAC/VDC 2SMD" "SMD FUSE" 1605,3690 r180 top value="1 AMP" (schematic designator F2)
F2_HDPRail "FUSE BRD MNT 1A 125VAC/VDC 2SMD" "SMD FUSE" 4045,3695 r180 top value="1 AMP" (schematic designator F2)
F3_HDNRail "FUSE BRD MNT 1A 125VAC/VDC 2SMD" "SMD FUSE" 1840,2744.88 r180 top value="1 AMP" (schematic designator F3)
F3_HDPRail "FUSE BRD MNT 1A 125VAC/VDC 2SMD" "SMD FUSE" 4225,2744.88 r180 top value="1 AMP" (schematic designator F3)
H1 "Header 3P Gold Unshrouded 0.100inch" "JUMPER 3P" 7440,2165 r90 top value=S1011EC-03-ND
J1 "DB9 Male" DB9M-RA 7765,384 r180 top locked value=6E17C-009P-AJ-121-ND
J4 "DB9 Female" DB9F-RA 3950,384 r180 top locked value=A32117-ND
P1 "Header 3H" Molex_156_RA_3 7735,3825 r90 top
P6 "Header 3H" Molex_156_RA_3 6197.5,3900 r90 top
P7 "BNC" BNC4 2200,35 r180 top locked value=A144890-ND
P8 "Header 4H" Molex_156_RA_4 420,1465 r90 top
P11 "Header 3H" Molex_156_RA_3 410,3800 r90 top
P12 "BNC" BNC4 915,35 r180 top locked value=A144890-ND
P13 "Header 2P 0.156inch Vertical" MOLEX_156_2 10975.12,4530.5 r180 top value=A31688-ND
P14 "Header 2P 0.156inch Vertical" MOLEX_156_2 8725,4530.5 r180 top locked value=A31688-ND
R1_DR1 "3.01K" CR3216-1206 6517.24,1845 r90 top (schematic designator R1)
R1_DR2 "3.01K" CR3216-1206 7852.24,1852.4 r90 top (schematic designator R1)
R1_DR3 "3.01K" CR3216-1206 9187.24,1850 r90 top (schematic designator R1)
R2_DR1 "100K OHM" CR3216-1206 6680,834.76 r180 top (schematic designator R2)
R2_DR2 "100K OHM" CR3216-1206 8015,834.88 r180 top (schematic designator R2)
R2_DR3 "100K OHM" CR3216-1206 9350,834.88 r180 top (schematic designator R2)
R3_DR1 "RES SMD 2.26K OHM 0.1% 1/4W 1206" CR3216-1206 6380,1850 r270 top value=2.26K (schematic designator R3)
R3_DR2 "RES SMD 2.26K OHM 0.1% 1/4W 1206" CR3216-1206 7725,1850 r270 top value=2.26K (schematic designator R3)
R3_DR3 "RES SMD 2.26K OHM 0.1% 1/4W 1206" CR3216-1206 9055,1855 r270 top value=2.26K (schematic designator R3)
R4_DR1 "1k" CR3216-1206 6570,949.76 r0 top (schematic designator R4)
R4_DR2 "1k" CR3216-1206 7905,949.88 r0 top (schematic designator R4)
R4_DR3 "1k" CR3216-1206 9240,945 r0 top (schematic designator R4)
R5_DR1 "0 ohm" CR3216-1206 6680,1119.76 r180 top (schematic designator R5)
R5_DR2 "0 ohm" CR3216-1206 8015,1119.88 r180 top (schematic designator R5)
R5_DR3 "0 ohm" CR3216-1206 9350,1119.88 r180 top (schematic designator R5)
R6_DR1 "NL" CR3216-1206 6070,964.76 r270 top (schematic designator R6)
R6_DR2 "NL" CR3216-1206 7405,964.88 r270 top (schematic designator R6)
R6_DR3 "NL" CR3216-1206 8740,964.88 r270 top (schematic designator R6)
R7_DR1 "1k" CR3216-1206 6355,949.76 r180 top (schematic designator R7)
R7_DR2 "1k" CR3216-1206 7690,949.88 r180 top (schematic designator R7)
R7_DR3 "1k" CR3216-1206 9020,945 r180 top (schematic designator R7)
R8_DR1 "0 ohm" CR3216-1206 6250,1119.76 r0 top (schematic designator R8)
R8_DR2 "0 ohm" CR3216-1206 7585,1119.88 r0 top (schematic designator R8)
R8_DR3 "0 ohm" CR3216-1206 8920,1119.88 r0 top (schematic designator R8)
R9_DR1 "RES SMD 2.26K OHM 0.1% 1/4W 1206" CR3216-1206 6835,1769.88 r90 top value=2.26K (schematic designator R9)
R9_DR2 "RES SMD 2.26K OHM 0.1% 1/4W 1206" CR3216-1206 8170,1770 r90 top value=2.26K (schematic designator R9)
R9_DR3 "RES SMD 2.26K OHM 0.1% 1/4W 1206" CR3216-1206 9505,1770 r90 top value=2.26K (schematic designator R9)
R10_DR1 "100K OHM" CR3216-1206 6240,834.76 r180 top (schematic designator R10)
R10_DR2 "100K OHM" CR3216-1206 7575,834.88 r180 top (schematic designator R10)
R10_DR3 "100K OHM" CR3216-1206 8910,834.88 r180 top (schematic designator R10)
R11_DR1 "3.01K" CR3216-1206 6667.24,1857.28 r90 top (schematic designator R11)
R11_DR2 "3.01K" CR3216-1206 8002.24,1857.4 r90 top (schematic designator R11)
R11_DR3 "3.01K" CR3216-1206 9337.24,1857.4 r90 top (schematic designator R11)
R12 "Res 1.3Kohm, 5W,5% Axial" AXIAL_RES_925 7250,3230 r90 top value="1.3Kohm 5W"
R13 "Relay DPDT SMD 12v DC" RELAY_G6K-2F-TR-DC5 7715,2830 r0 top
R14 "0 Ohm" CR3216-1206 8210,2730 r180 top value="0 ohm"
R15 "0 Ohm" CR3216-1206 7495,2730 r180 top value="0 ohm"
R16 "0 Ohm" CR3216-1206 8210,2625 r180 top value="0 ohm"
R17 "SMD Res 3.9K 0.1% 0.25W 1206" CR3216-1206 7255,2592 r90 top value=3.9K
R18 "SMD Res 3.9K 0.1% 0.25W 1206" CR3216-1206 7440,2555 r270 top value=3.9K
R19 "39.2K" CR3216-1206 10770,1850 r0 top
R20 "39.2K" CR3216-1206 10550,1850 r0 top
R21 "39.2K" CR3216-1206 10835,925 r0 top
R22 "39.2K" CR3216-1206 10610,925 r0 top
R23 "10K Resistor 1206 0.25W 0.1%" CR3216-1206 6542.49,2630 r0 top value=10K
R24 "10K Resistor 1206 0.25W 0.1%" CR3216-1206 6283,2450 r0 top value=10K
R25 "10K Resistor 1206 0.25W 0.1%" CR3216-1206 6278,2575 r0 top value=10K
R26_DifferentialDriver "4.99K" CR3216-1206 6384.88,3415 r180 top (schematic designator R26)
R26_HDNR_I_DifferentialDriver "4.99K" CR3216-1206 2660.12,1390 r270 top (schematic designator R26)
R26_HDNR_V_DifferentialDriver "4.99K" CR3216-1206 3625,1389.88 r270 top (schematic designator R26)
R26_HDPR_I_DifferentialDriver "4.99K" CR3216-1206 4585,1390 r270 top (schematic designator R26)
R26_HDPR_V_DifferentialDriver "4.99K" CR3216-1206 5570,1410 r270 top (schematic designator R26)
R27_DifferentialDriver "4.99K" CR3216-1206 6159.88,3185 r90 top (schematic designator R27)
R27_HDNR_I_DifferentialDriver "4.99K" CR3216-1206 2510.12,1445 r0 top (schematic designator R27)
R27_HDNR_V_DifferentialDriver "4.99K" CR3216-1206 3475,1444.88 r0 top (schematic designator R27)
R27_HDPR_I_DifferentialDriver "4.99K" CR3216-1206 4385,1470 r0 top (schematic designator R27)
R27_HDPR_V_DifferentialDriver "4.99K" CR3216-1206 5385,1470 r0 top (schematic designator R27)
R28_DifferentialDriver "0 Ohm" CR3216-1206 6129.88,3345 r180 top value="0 ohm" (schematic designator R28)
R28_HDNR_I_DifferentialDriver "0 Ohm" CR3216-1206 2615.12,935 r270 top value="0 ohm" (schematic designator R28)
R28_HDNR_V_DifferentialDriver "0 Ohm" CR3216-1206 3580,934.88 r270 top value="0 ohm" (schematic designator R28)
R28_HDPR_I_DifferentialDriver "0 Ohm" CR3216-1206 4565,900 r270 top value="0 ohm" (schematic designator R28)
R28_HDPR_V_DifferentialDriver "0 Ohm" CR3216-1206 5535,905 r270 top value="0 ohm" (schematic designator R28)
R29_DifferentialDriver "4.99K" CR3216-1206 6719.88,3245 r0 top (schematic designator R29)
R29_HDNR_I_DifferentialDriver "4.99K" CR3216-1206 2405.12,935 r270 top (schematic designator R29)
R29_HDNR_V_DifferentialDriver "4.99K" CR3216-1206 3370,934.88 r270 top (schematic designator R29)
R29_HDPR_I_DifferentialDriver "4.99K" CR3216-1206 4330,894.88 r270 top (schematic designator R29)
R29_HDPR_V_DifferentialDriver "4.99K" CR3216-1206 5300,900 r270 top (schematic designator R29)
R30_DifferentialDriver "4.99K" CR3216-1206 6719.88,3150 r180 top (schematic designator R30)
R30_HDNR_I_DifferentialDriver "4.99K" CR3216-1206 2245,1085 r0 top (schematic designator R30)
R30_HDNR_V_DifferentialDriver "4.99K" CR3216-1206 3215,1090 r0 top (schematic designator R30)
R30_HDPR_I_DifferentialDriver "4.99K" CR3216-1206 4155,1065 r0 top (schematic designator R30)
R30_HDPR_V_DifferentialDriver "4.99K" CR3216-1206 5110,1065 r0 top (schematic designator R30)
R31_DifferentialDriver "0 Ohm" CR3216-1206 6840,3420 r0 top value="0 ohm" (schematic designator R31)
R31_HDNR_I_DifferentialDriver "0 Ohm" CR3216-1206 2510.12,935 r270 top value="0 ohm" (schematic designator R31)
R31_HDNR_V_DifferentialDriver "0 Ohm" CR3216-1206 3475,934.88 r270 top value="0 ohm" (schematic designator R31)
R31_HDPR_I_DifferentialDriver "0 Ohm" CR3216-1206 4450,895 r270 top value="0 ohm" (schematic designator R31)
R31_HDPR_V_DifferentialDriver "0 Ohm" CR3216-1206 5420,905 r270 top value="0 ohm" (schematic designator R31)
R32_HDNRail "RES SMD 2.61K OHM 0.1% 1/4W 1206" CR3216-1206 1807,2453 r180 top value=2.61K (schematic designator R32)
R32_HDPRail "RES SMD 2.61K OHM 0.1% 1/4W 1206" CR3216-1206 4192,2453 r180 top value=2.61K (schematic designator R32)
R33_HDNRail "SMD Res 1206 100K 0.25W" CR3216-1206 1450,2098 r90 top value=100K (schematic designator R33)
R33_HDPRail "SMD Res 1206 100K 0.25W" CR3216-1206 3835,2098 r90 top value=100K (schematic designator R33)
R34_HDNRail "SMD Res 1206 100K 0.25W" CR3216-1206 1570,2098 r90 top value=100K (schematic designator R34)
R34_HDPRail "SMD Res 1206 100K 0.25W" CR3216-1206 3955,2098 r90 top value=100K (schematic designator R34)
R35_HDNRail "RES SMD 0.1 OHM 1% 25W D2PAK" D2PAK_RES 1355,3369.88 r270 top value=0.1R (schematic designator R35)
R35_HDPRail "RES SMD 0.1 OHM 1% 25W D2PAK" D2PAK_RES 3740,3369.88 r270 top value=0.1R (schematic designator R35)
R36_HDNRail "SMD Res 1206 100K 0.25W" CR3216-1206 1570,2350 r270 top value=100K (schematic designator R36)
R36_HDPRail "SMD Res 1206 100K 0.25W" CR3216-1206 3955,2350 r270 top value=100K (schematic designator R36)
R37_HDNRail "SMD Res 1206 100K 0.25W" CR3216-1206 1450,2350 r270 top value=100K (schematic designator R37)
R37_HDPRail "SMD Res 1206 100K 0.25W" CR3216-1206 3835,2350 r270 top value=100K (schematic designator R37)
R38_HDNRail "SMD Res 1206 23.2K 0.1% 0.25W" CR3216-1206 2735,2991 r90 top value=23.2K (schematic designator R38)
R38_HDPRail "SMD Res 1206 23.2K 0.1% 0.25W" CR3216-1206 5120,2991 r90 top value=23.2K (schematic designator R38)
R39_HDNRail "SMD Res 1206 23.2K 0.1% 0.25W" CR3216-1206 2783,2203 r0 top value=23.2K (schematic designator R39)
R39_HDPRail "SMD Res 1206 23.2K 0.1% 0.25W" CR3216-1206 5178,2203 r0 top value=23.2K (schematic designator R39)
R40_HDNRail "SMD Res 1.58K 0.1% 0.25W 1206" CR3216-1206 2797,2818 r180 top value=1.58K (schematic designator R40)
R40_HDPRail "SMD Res 1.58K 0.1% 0.25W 1206" CR3216-1206 5188,2818 r180 top value=1.58K (schematic designator R40)
R41_HDNRail "SMD Res 1.58K 0.1% 0.25W 1206" CR3216-1206 2615,2016 r90 top value=1.58K (schematic designator R41)
R41_HDPRail "SMD Res 1.58K 0.1% 0.25W 1206" CR3216-1206 5000,2016 r90 top value=1.58K (schematic designator R41)
R42_HDNRail "10K Resistor 1206 0.25W 0.1%" CR3216-1206 2445,2996 r90 top value=10K (schematic designator R42)
R42_HDPRail "10K Resistor 1206 0.25W 0.1%" CR3216-1206 4830,2996 r90 top value=10K (schematic designator R42)
R43_HDNRail "4.99K" CR3216-1206 2585,2991.88 r270 top (schematic designator R43)
R43_HDPRail "4.99K" CR3216-1206 4970,2991.88 r270 top (schematic designator R43)
R44_HDNRail "0 Ohm" CR3216-1206 2470,3410 r270 top value="0 ohm" (schematic designator R44)
R44_HDPRail "0 Ohm" CR3216-1206 4855,3410 r270 top value="0 ohm" (schematic designator R44)
R45_HDNRail "0 Ohm" CR3216-1206 2590,3410 r270 top value="0 ohm" (schematic designator R45)
R45_HDPRail "0 Ohm" CR3216-1206 4975,3410 r270 top value="0 ohm" (schematic designator R45)
R46_HDNRail "0 Ohm" CR3216-1206 2280,3715 r180 top value="0 ohm" (schematic designator R46)
R46_HDPRail "0 Ohm" CR3216-1206 4665,3715 r180 top value="0 ohm" (schematic designator R46)
R47 "SMD Res 249Ohm 0.1% 0.25W 1206" CR3216-1206 10598,4090.5 r0 top value=249
R48 "SMD Res 2.74K 0.1%  0.25W 1206" CR3216-1206 10602,3670.5 r180 top value=2.74K
R49 "SMD Res 1.33K 0.1% 0.25W 1206" CR3216-1206 9478,4140.5 r0 top value=1.33K
R50 "SMD Res 120ohm 0.1% 0.25W  1206" CR3216-1206 9472,3925.5 r180 top value=120R
R51 "10K Resistor 1206 0.25W 0.1%" CR3216-1206 5615,338 r90 top value=10K
R52 "10K Resistor 1206 0.25W 0.1%" CR3216-1206 6130,237 r270 top value=10K
R53 "10K Resistor 1206 0.25W 0.1%" CR3216-1206 10520.12,4433.5 r90 top value=10K
R54 "10K Resistor 1206 0.25W 0.1%" CR3216-1206 8555,4197.5 r270 top value=10K
TP1_DR1 "TESTPT" TP3heater 6995,1594.76 r0 top value=36-5016CT-ND (schematic designator TP1)
TP1_DR2 "TESTPT" TP3heater 8330,1594.88 r0 top value=36-5016CT-ND (schematic designator TP1)
TP1_DR3 "TESTPT" TP3heater 9665,1594.88 r0 top value=36-5016CT-ND (schematic designator TP1)
TP2 "TESTPT" TP3heater 7870,2255 r0 top value=36-5016CT-ND
TP3 "TESTPT" TP3heater 8175,2255 r0 top value=36-5016CT-ND
TP4 "TESTPT" TP3heater 8220,2960 r0 top value=36-5016CT-ND
TP5 "TESTPT" TP3heater 10590,1140 r0 top value=36-5016CT-ND
TP6 "TESTPT" TP3heater 10530,160 r270 top value=36-5016CT-ND
TP7 "TESTPT" TP3heater 6770,2630 r180 top value=36-5016CT-ND
TP8_DifferentialDriver "TESTPT" TP3heater 6139.76,3575 r0 top value=36-5016CT-ND (schematic designator TP8)
TP8_HDNR_I_DifferentialDriver "TESTPT" TP3heater 2800.12,895 r0 top value=36-5016CT-ND (schematic designator TP8)
TP8_HDNR_V_DifferentialDriver "TESTPT" TP3heater 3765,894.88 r0 top value=36-5016CT-ND (schematic designator TP8)
TP8_HDPR_I_DifferentialDriver "TESTPT" TP3heater 4750,895 r0 top value=36-5016CT-ND (schematic designator TP8)
TP8_HDPR_V_DifferentialDriver "TESTPT" TP3heater 5720,909.65 r0 top value=36-5016CT-ND (schematic designator TP8)
TP9_DifferentialDriver "TESTPT" TP3heater 6750,3575 r0 top value=36-5016CT-ND (schematic designator TP9)
TP9_HDNR_I_DifferentialDriver "TESTPT" TP3heater 2224.88,875 r0 top value=36-5016CT-ND (schematic designator TP9)
TP9_HDNR_V_DifferentialDriver "TESTPT" TP3heater 3190,879.76 r0 top value=36-5016CT-ND (schematic designator TP9)
TP9_HDPR_I_DifferentialDriver "TESTPT" TP3heater 4150,840 r0 top value=36-5016CT-ND (schematic designator TP9)
TP9_HDPR_V_DifferentialDriver "TESTPT" TP3heater 5125,855.12 r0 top value=36-5016CT-ND (schematic designator TP9)
TP10_HDNRail "TESTPT" TP3heater 1915,1913 r90 top value=36-5016CT-ND (schematic designator TP10)
TP10_HDPRail "TESTPT" TP3heater 4300,1913 r90 top value=36-5016CT-ND (schematic designator TP10)
TP11_HDNRail "TESTPT" TP3heater 2145,2828 r0 top value=36-5016CT-ND (schematic designator TP11)
TP11_HDPRail "TESTPT" TP3heater 4530,2828 r0 top value=36-5016CT-ND (schematic designator TP11)
TP12_HDNRail "TESTPT" TP3heater 2820,1888 r270 top value=36-5016CT-ND (schematic designator TP12)
TP12_HDPRail "TESTPT" TP3heater 5205,1888 r270 top value=36-5016CT-ND (schematic designator TP12)
TP13_HDNRail "TESTPT" TP3heater 2805,2599.88 r180 top value=36-5016CT-ND (schematic designator TP13)
TP13_HDPRail "TESTPT" TP3heater 5190,2599.88 r180 top value=36-5016CT-ND (schematic designator TP13)
TP14_HDNRail "TESTPT" TP3heater 2160,3415 r0 top value=36-5016CT-ND (schematic designator TP14)
TP14_HDPRail "TESTPT" TP3heater 4545,3415 r0 top value=36-5016CT-ND (schematic designator TP14)
TP15 "TESTPT" TP3heater 7595,3485 r0 top value=36-5016CT-ND
TP16 "TESTPT" TP3heater 10920,4090 r0 top value=36-5016CT-ND
TP17 "TESTPT" TP3heater 7895,3465 r0 top value=36-5016CT-ND
TP18 "TESTPT" TP3heater 8220,3430 r0 top value=36-5016CT-ND
TP19 "TESTPT" TP3heater 8795,4085.5 r0 top value=36-5016CT-ND
TP20_HDNRail "TESTPT" TP3heater 1360,2755 r90 top value=36-5016CT-ND (schematic designator TP20)
TP20_HDPRail "TESTPT" TP3heater 3750,2755 r90 top value=36-5016CT-ND (schematic designator TP20)
TP21 "TESTPT" TP3heater 4515,4190 r0 top value=36-5016CT-ND
TP22 "TESTPT" TP3heater 260,3290 r0 top value=36-5016CT-ND
TP23 "TESTPT" TP3heater 725,855 r0 top value=36-5016CT-ND
TP24 "TESTPT" TP3heater 6775,4055 r0 top value=36-5016CT-ND
U1_DR1 "LT1125CS" SOIC127P1030-16N 6494.88,1429.88 r90 top (schematic designator U1)
U1_DR2 "LT1125CS" SOIC127P1030-16N 7829.88,1430 r90 top (schematic designator U1)
U1_DR3 "LT1125CS" SOIC127P1030-16N 9164.88,1430 r90 top (schematic designator U1)
U2 "Transistor Switch NPN General Purpose 40v 1Amp" SOT-23-3 7205,2820 r0 top value=MMBT2222A
U3 "OP27GSZ" SO8_N 10500,1565 r270 top value=OP27GSZ-ND
U4 "OP27GSZ" SO8_N 10525,660 r270 top value=OP27GSZ-ND
U5 "OP27GSZ" SO8_N 6559.49,2425 r0 top value=OP27GSZ-ND
U6_DifferentialDriver "AD8672" SOIC_8P_ 6290,3290 r0 top (schematic designator U6)
U6_HDNR_I_DifferentialDriver "AD8672" SOIC_8P_ 2560.12,1335 r270 top (schematic designator U6)
U6_HDNR_V_DifferentialDriver "AD8672" SOIC_8P_ 3525,1334.88 r270 top (schematic designator U6)
U6_HDPR_I_DifferentialDriver "AD8672" SOIC_8P_ 4490,1315 r270 top (schematic designator U6)
U6_HDPR_V_DifferentialDriver "AD8672" SOIC_8P_ 5460,1334.88 r270 top (schematic designator U6)
U7_HDNRail "AD620BRZ" SOIC_8P_ 1695,2333 r0 top value=AD620BRZ-R7CT-ND (schematic designator U7)
U7_HDPRail "AD620BRZ" SOIC_8P_ 4080,2333 r0 top value=AD620BRZ-R7CT-ND (schematic designator U7)
U8_HDNRail "OP27GSZ" SO8_N 2460,2259.88 r180 top value=OP27GSZ-ND (schematic designator U8)
U8_HDPRail "OP27GSZ" SO8_N 4845,2260 r180 top value=OP27GSZ-ND (schematic designator U8)
U9_HDNRail "OP27GSZ" SO8_N 2480,2729.88 r270 top value=OP27GSZ-ND (schematic designator U9)
U9_HDPRail "OP27GSZ" SO8_N 4865,2729.88 r270 top value=OP27GSZ-ND (schematic designator U9)
U10_HDNRail "OP27GSZ" SO8_N 2525,3665 r90 top value=OP27GSZ-ND (schematic designator U10)
U10_HDPRail "OP27GSZ" SO8_N 4910,3665 r90 top value=OP27GSZ-ND (schematic designator U10)
U11 "Linear Voltage Reg + 1.25v to 37v 1.5A TO-220-3" MY_TO220_HEATSINK 10215,3255.5 r180 top locked value=LM317TNS/NOPB-ND
U12 "Linear Voltage Reg -1.2v to -37v  1.5A TO-220-3" MY_TO220_HEATSINK 9140,3255.5 r180 top locked value=LM337TNS/NOPB-ND

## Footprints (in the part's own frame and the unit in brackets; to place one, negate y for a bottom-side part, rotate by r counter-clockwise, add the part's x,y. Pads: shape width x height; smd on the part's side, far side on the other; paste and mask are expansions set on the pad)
2916 [mil]
  rect 70x120 smd: 1(0,0) 2(272,0)
  silkscreen extent 62,-50 194,75, body extent -10,-90 282,90, height 112
AXIAL_RES_925 [mil] "Power Resistor 5W"
  round 75 hole 52: 1(0,0) 2(1000,0)
  body extent -10,-211 1010,211, height 414
BNC4 [mil] "BNC right angle PCB, low profile"
  round 70 hole 32: 1(0,-460) 2(-100,-460)
  round 120 hole 80: 3(-200,-260) 4(200,-260)
  silkscreen extent -300,-560 300,-10, body extent -286,-542 285,852, height 516
CAP_FILM_0.689INCH [mil]
  round 75 hole 52: 1(0,0) 2(689,0)
  silkscreen extent -20,-213 709,213, body extent -13,-10 702,10, height 10
CAP_FILM_0.886INCH [mil]
  round 75 hole 52: 1(0,0) 2(886,0)
  silkscreen extent -69,-227 955,227, body extent -14,-10 899,10, height 10
CAP_FILM_POLY_0.197INCH [mil]
  round 48 hole 28: 1(0,0) 2(197,0)
  silkscreen extent -20,-59 220,59, body extent -13,-10 210,10, height 10
CC3216-1206 [mm] "Chip Capacitor; Body 3.2 x 1.6 mm (LxW typ)"
  rect 1.6x1.8 smd: 1(-1.4,0) 2(1.4,0)
  silkscreen extent -0.3,-0.8 0.3,0.8, body extent -1.85,-0.97 1.85,0.97, height 0.88
CR3216-1206 [mm] "Chip Resistor; Body 3.2 x 1.6 mm (LxW typ)"
  rect 1.6x1.8 smd: 1(-1.4,0) 2(1.4,0)
  silkscreen extent -0.3,-0.8 0.3,0.8, body extent -1.67,-0.86 1.68,0.87, height 0.85
D2PAK_RES [mil] "Res_D2PAK"
  rect 80x160 smd: 1(0,0) 3(200,0)
  rect 470x400 smd: ""(100,400)
  silkscreen extent -156,149 357,645, body extent -101,-36 304,637, height 152
DB9F-RA [mm] "Receptiacle; D Subminiature 9 Position; Right Angle"
  rect 1.69x1.69 hole 1.09: 1(-5.54,-1.42)
  round 1.69 hole 1.09: 2(-2.77,-1.42) 3(0,-1.42) 4(2.77,-1.42) 5(5.54,-1.42) 6(-4.155,1.42) 7(-1.385,1.42) 8(1.385,1.42) 9(4.155,1.42)
  round 4.76 hole 3.26: 10(-12.495,0) 11(12.495,0)
  silkscreen extent -15.4,-2.9 15.4,9.5, body extent -15.49,-3.17 15.49,15.72, height 12.62
DB9M-RA [mm] "Plug; D Subminiature 9 Position; Right Angle"
  rect 1.69x1.69 hole 1.09: 1(5.54,-1.42)
  round 1.69 hole 1.09: 2(2.77,-1.42) 3(0,-1.42) 4(-2.77,-1.42) 5(-5.54,-1.42) 6(4.155,1.42) 7(1.385,1.42) 8(-1.385,1.42) 9(-4.155,1.42)
  round 4.76 hole 3.26: 10(12.495,0) 11(-12.495,0)
  silkscreen extent -15.4,-2.9 15.4,9.5, body extent -15.52,-3.24 15.52,15.37, height 12.62
DIODE_SE20AFJ-M3/6A [mil]
  rect 70x80 smd: 1(0,0) 2(170,0)
  silkscreen extent 60,-20 108,21
DIODE_SMB [mil] "D0-214AA"
  rect 112x96 smd: 1(0,0) 2(182.5,0)
  silkscreen extent -35,-90 233,90, body extent -26,-85 212,85, height 98
"JUMPER 3P" [mil]
  round 58 hole 40: 1(0,0) 2(100,0) 3(200,0)
  silkscreen extent -35,-50 235,50
MOLEX_156_2 [mil] "2 Pin Molex, 0.156mil Spacing"
  rect 110x110 hole 80: 1(0,0)
  round 110 hole 80: 2(156,0)
  silkscreen extent -78,-120 235,180
Molex_156_RA_3 [mil] "3 Pin Molex, 0.156mil Spacing, Right Angle"
  rect 110x110 hole 80: 1(0,0)
  round 110 hole 80: 2(0,-156) 3(0,-312)
  silkscreen extent 213,-382 792,70, body extent -24,-385 791,77, height 394
Molex_156_RA_4 [mil]
  rect 110x110 hole 80: 1(0,0)
  round 110 hole 80: 2(0,-156) 3(0,-312) 4(0,-468)
  silkscreen extent 213,-538 792,70, body extent -26,-540 790,78, height 394
"my LUMEX Dual LED" [mil]
  rect 52x52 hole 32: 1(0,0)
  round 52 hole 32: 2(0,-100) 3(-100,0) 4(-100,-100)
  silkscreen extent -320,-140 45,40, body extent -379,-135 45,35, height 380
MY_TO220_HEATSINK [mil]
  rrect50% 62x62 hole 40: 1(-100,-680)
  rect 62x62 hole 40: 2(0,-680) 3(100,-680)
  round 200 hole 155: 4(0,0)
  round 100 hole 75: 5(0,844.5)
  silkscreen extent -205,-620 200,1025
RELAY_G6K-2F-TR-DC5 [mil]
  rect 140x47 smd: 1(0,0)
  oval 140x47 smd: 2(0,-100) 3(0,-200) 4(0,-300) 5(280,-300) 6(280,-200) 7(280,-100) 8(280,0)
  silkscreen extent 95,-360 185,50
"SMD FUSE" [mil]
  rect 170x160 smd: 1(0,0) 2(260,0)
  silkscreen extent -68,-102 328,103, body extent -80,-70 337,70, height 70
SO8_N [mm] "SOIC, 8-Leads, Body 4.9x3.9mm, Pitch 1.27mm, IPC Medium Density"
  oval 2.2x0.6 smd: 1(-2.4,1.905) 2(-2.4,0.635) 3(-2.4,-0.635) 4(-2.4,-1.905) 5(2.4,-1.905) 6(2.4,-0.635) 7(2.4,0.635) 8(2.4,1.905)
  silkscreen extent -2.52,-2.5 0.9,2.88, body extent -2,-2.5 2,2.5, height 1.75
SOD-123F [mil]
  rect 35x48 smd: 1(0,0) 2(120.5,0)
  silkscreen extent -15,-37 125,37, body extent -10,-27 129,27, height 42
SOIC127P1030-16N [mm] "SOIC, 16-Leads, Body 10.3x7.5mm, Pitch 1.27mm, IPC Medium Density"
  oval 2.3x0.6 smd: 1(-4.55,4.445) 2(-4.55,3.175) 3(-4.55,1.905) 4(-4.55,0.635) 5(-4.55,-0.635) 6(-4.55,-1.905) 7(-4.55,-3.175) 8(-4.55,-4.445) 9(4.55,-4.445) 10(4.55,-3.175) 11(4.55,-1.905) 12(4.55,-0.635) 13(4.55,0.635) 14(4.55,1.905) 15(4.55,3.175) 16(4.55,4.445)
  silkscreen extent -4.67,-5.25 3,5.42, body extent -3.75,-5.25 3.75,5.25, height 2.65
SOIC_8P_ [mil]
  rrect50% 80x30 smd: 1(0,0)
  rect 80x30 smd: 2(0,-50) 3(0,-100) 4(0,-150) 5(230,-150) 6(230,-100) 7(230,-50) 8(230,0)
  silkscreen extent 60,-184 170,40, body extent -33,-180 264,35, height 72
SOT-23-3 [mil]
  rect 48x60 smd: 1(0,0) 2(75,0) 3(37,85)
  body extent -38,-13 113,97, height 20
SOT-23A [mm] "SOT-23; 3 Leads; Body 3.1 x 2.5 mm, inc. leads (LxW max)"
  rect 0.85x1 smd: 1(-0.95,-1.2) 2(0.95,-1.2) 3(0,1.2)
  silkscreen extent -2.05,-1.32 1.28,1.2
TP3heater [mil] "Testpoint SMD compact"
  rect 185x135 smd: 1(0,0)
  body extent -75,-56 75,56, height 90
